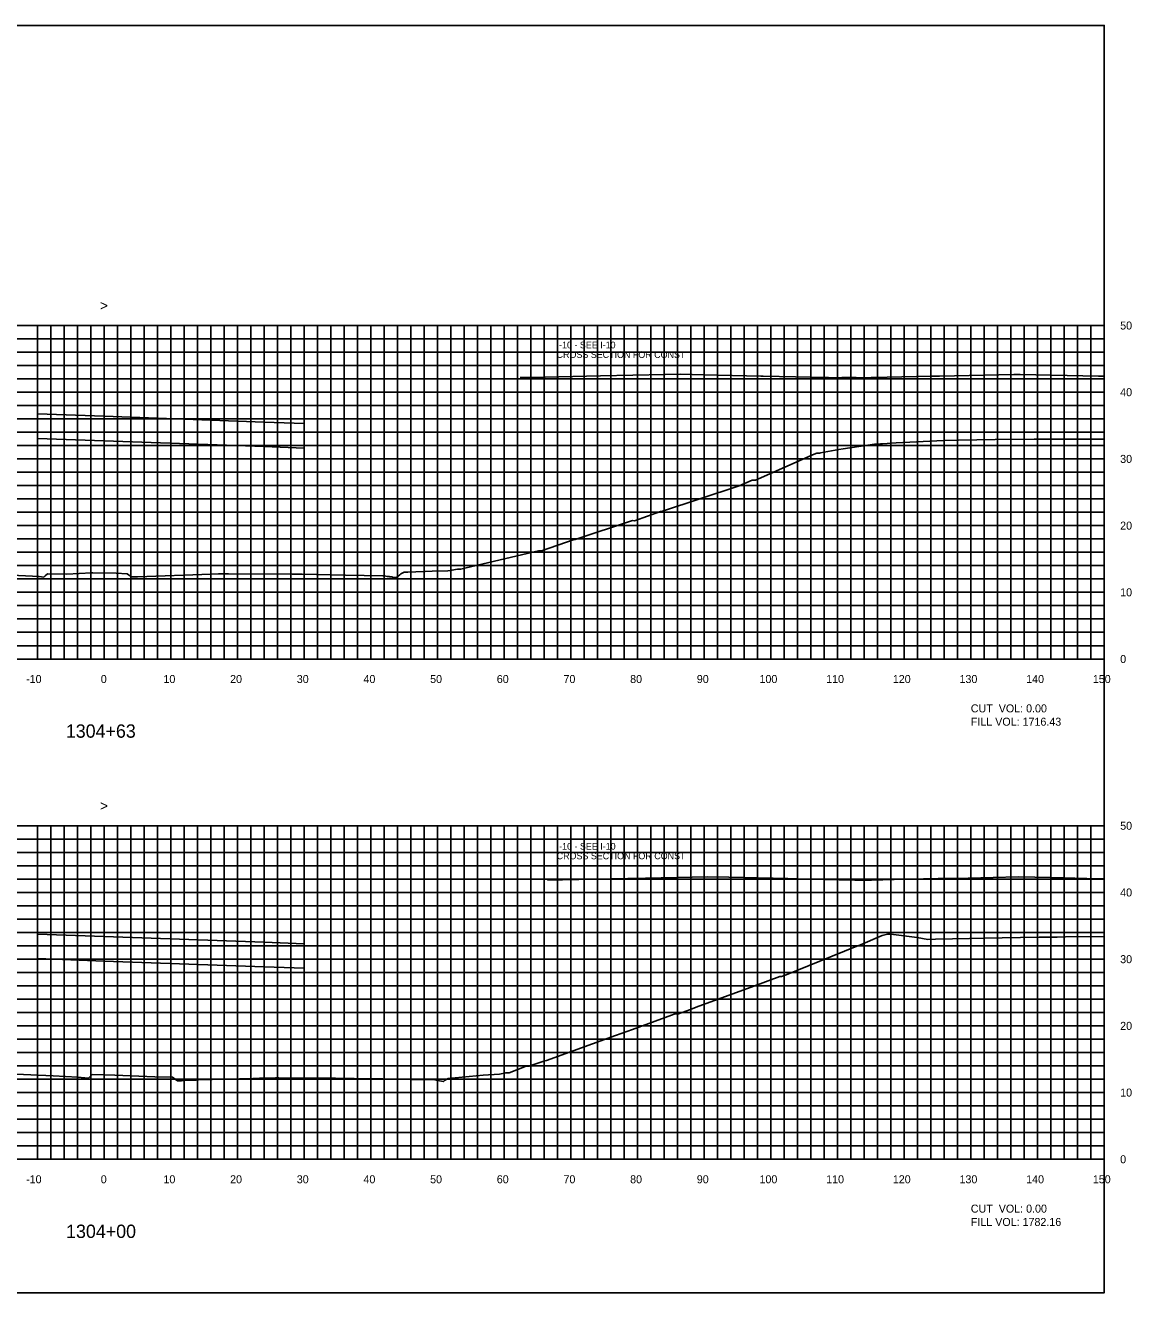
# Model space of a CAD drawing. Extents: x 1797714 to 1804825, y 249015 to 250269.
# Drawn here: x 1803639.2 to 1803805.1, y 250079.4 to 250269.4 of the extents above; entities that cross this region are included whole.
import ezdxf

# ---------------------------------------------------------------- set-up
doc = ezdxf.new("R2010")
doc.units = 0
for name, color, linetype in [('1', 7, 'Continuous'), ('10', 7, 'Continuous'), ('3', 7, 'Continuous'), ('31', 7, 'Continuous'), ('60', 7, 'Continuous'), ('ANNO-TXT', 7, 'Continuous'), ('BRG-DECK', 7, 'Continuous'), ('CL-CNST', 7, 'Continuous'), ('Level 62', 7, 'Continuous'), ('M-ROADS', 7, 'Continuous')]:
    doc.layers.add(name, color=color, linetype=linetype)

msp = doc.modelspace()

# ---------------------------------------------------------------- linework, layer by layer
msp.add_lwpolyline([(1803501, 250079.43), (1803801, 250079.43), (1803801, 250269.43), (1803501, 250269.43)], close=True)
at = {"layer": '60'}
for p, q in [((1803801, 250174.43), (1803801, 250224.43)), ((1803801.06, 250224.43), (1803801, 250224.43)), ((1803801.06, 250214.43), (1803801, 250214.43)), ((1803801.06, 250204.43), (1803801, 250204.43)), ((1803801.06, 250194.43), (1803801, 250194.43)), ((1803801.06, 250184.43), (1803801, 250184.43)), ((1803501, 250174.43), (1803801, 250174.43)), ((1803641, 250174.37), (1803641, 250174.43)), ((1803651, 250174.37), (1803651, 250174.43)), ((1803661, 250174.37), (1803661, 250174.43)), ((1803671, 250174.37), (1803671, 250174.43)), ((1803681, 250174.37), (1803681, 250174.43)), ((1803691, 250174.37), (1803691, 250174.43)), ((1803701, 250174.37), (1803701, 250174.43)), ((1803711, 250174.37), (1803711, 250174.43)), ((1803721, 250174.37), (1803721, 250174.43)), ((1803731, 250174.37), (1803731, 250174.43)), ((1803741, 250174.37), (1803741, 250174.43)), ((1803751, 250174.37), (1803751, 250174.43)), ((1803761, 250174.37), (1803761, 250174.43)), ((1803771, 250174.37), (1803771, 250174.43)), ((1803781, 250174.37), (1803781, 250174.43)), ((1803791, 250174.37), (1803791, 250174.43)), ((1803801, 250174.37), (1803801, 250174.43)), ((1803801.06, 250174.43), (1803801, 250174.43)), ((1803801, 250099.43), (1803801, 250149.43)), ((1803801.06, 250149.43), (1803801, 250149.43)), ((1803801.06, 250139.43), (1803801, 250139.43)), ((1803801.06, 250129.43), (1803801, 250129.43)), ((1803801.06, 250119.43), (1803801, 250119.43)), ((1803801.06, 250109.43), (1803801, 250109.43)), ((1803501, 250099.43), (1803801, 250099.43)), ((1803641, 250099.37), (1803641, 250099.43)), ((1803651, 250099.37), (1803651, 250099.43)), ((1803661, 250099.37), (1803661, 250099.43)), ((1803671, 250099.37), (1803671, 250099.43)), ((1803681, 250099.37), (1803681, 250099.43)), ((1803691, 250099.37), (1803691, 250099.43)), ((1803701, 250099.37), (1803701, 250099.43)), ((1803711, 250099.37), (1803711, 250099.43)), ((1803721, 250099.37), (1803721, 250099.43)), ((1803731, 250099.37), (1803731, 250099.43)), ((1803741, 250099.37), (1803741, 250099.43)), ((1803751, 250099.37), (1803751, 250099.43)), ((1803761, 250099.37), (1803761, 250099.43)), ((1803771, 250099.37), (1803771, 250099.43)), ((1803781, 250099.37), (1803781, 250099.43)), ((1803791, 250099.37), (1803791, 250099.43)), ((1803801, 250099.37), (1803801, 250099.43)), ((1803801.06, 250099.43), (1803801, 250099.43))]:
    msp.add_line(p, q, dxfattribs=at)
at = {"layer": 'BRG-DECK'}
for points in [[(1803681, 250206.06), (1803681, 250209.74), (1803675, 250209.95), (1803651, 250210.82), (1803641, 250211.18), (1803641, 250207.5), (1803651, 250207.14), (1803675, 250206.27)], [(1803681, 250128.07), (1803681, 250131.75), (1803675, 250131.97), (1803651, 250132.83), (1803641, 250133.19), (1803641, 250129.51), (1803651, 250129.15), (1803675, 250128.29)]]:
    msp.add_lwpolyline(points, close=True, dxfattribs=at)
at = {"layer": 'CL-CNST'}
for points in [[(1803713.39, 250216.62), (1803715.06, 250216.65), (1803725.43, 250216.88), (1803735.14, 250217.08), (1803737.47, 250217.13), (1803740.95, 250217.06), (1803749.51, 250216.86), (1803749.84, 250216.86), (1803759.55, 250216.64), (1803759.63, 250216.64), (1803760.8, 250216.61), (1803760.8, 250216.61), (1803760.89, 250216.61), (1803761.66, 250216.63), (1803762.67, 250216.65), (1803763.78, 250216.63), (1803765.01, 250216.61)], [(1803765.01, 250216.61), (1803766.06, 250216.63), (1803766.27, 250216.63), (1803775.05, 250216.82), (1803776.32, 250216.85), (1803787.46, 250217.09), (1803788.38, 250217.11), (1803800.14, 250216.84), (1803800.44, 250216.83), (1803801, 250216.82)], [(1803641, 250211.18), (1803651, 250210.82), (1803675, 250209.95), (1803681, 250209.74)], [(1803717.52, 250141.25), (1803719.73, 250141.3), (1803729.53, 250141.51), (1803732.21, 250141.57), (1803741.55, 250141.77), (1803744.7, 250141.7), (1803753.57, 250141.5), (1803756.56, 250141.44), (1803763.58, 250141.28), (1803763.98, 250141.27), (1803764.83, 250141.25), (1803764.83, 250141.25), (1803764.83, 250141.25), (1803765.24, 250141.26), (1803766.08, 250141.28), (1803769.48, 250141.35), (1803776.1, 250141.5), (1803780.6, 250141.59), (1803788.11, 250141.76), (1803793.08, 250141.65), (1803800.13, 250141.49), (1803801, 250141.47)], [(1803641, 250133.19), (1803651, 250132.83), (1803675, 250131.97), (1803681, 250131.75)]]:
    msp.add_lwpolyline(points, dxfattribs=at)
at = {"layer": 'Level 62'}
for p, q in [((1803501, 250224.43), (1803801, 250224.43)), ((1803641, 250174.43), (1803641, 250224.43)), ((1803643, 250174.43), (1803643, 250224.43)), ((1803645, 250174.43), (1803645, 250224.43)), ((1803647, 250174.43), (1803647, 250224.43)), ((1803649, 250174.43), (1803649, 250224.43)), ((1803651, 250174.43), (1803651, 250224.43)), ((1803653, 250174.43), (1803653, 250224.43)), ((1803655, 250174.43), (1803655, 250224.43)), ((1803657, 250174.43), (1803657, 250224.43)), ((1803659, 250174.43), (1803659, 250224.43)), ((1803661, 250174.43), (1803661, 250224.43)), ((1803663, 250174.43), (1803663, 250224.43)), ((1803665, 250174.43), (1803665, 250224.43)), ((1803667, 250174.43), (1803667, 250224.43)), ((1803669, 250174.43), (1803669, 250224.43)), ((1803671, 250174.43), (1803671, 250224.43)), ((1803673, 250174.43), (1803673, 250224.43)), ((1803675, 250174.43), (1803675, 250224.43)), ((1803677, 250174.43), (1803677, 250224.43)), ((1803679, 250174.43), (1803679, 250224.43)), ((1803681, 250174.43), (1803681, 250224.43)), ((1803683, 250174.43), (1803683, 250224.43)), ((1803685, 250174.43), (1803685, 250224.43)), ((1803687, 250174.43), (1803687, 250224.43)), ((1803689, 250174.43), (1803689, 250224.43)), ((1803691, 250174.43), (1803691, 250224.43)), ((1803693, 250174.43), (1803693, 250224.43)), ((1803695, 250174.43), (1803695, 250224.43)), ((1803697, 250174.43), (1803697, 250224.43)), ((1803699, 250174.43), (1803699, 250224.43)), ((1803701, 250174.43), (1803701, 250224.43)), ((1803703, 250174.43), (1803703, 250224.43)), ((1803705, 250174.43), (1803705, 250224.43)), ((1803707, 250174.43), (1803707, 250224.43)), ((1803709, 250174.43), (1803709, 250224.43)), ((1803711, 250174.43), (1803711, 250224.43)), ((1803713, 250174.43), (1803713, 250224.43)), ((1803715, 250174.43), (1803715, 250224.43)), ((1803717, 250174.43), (1803717, 250224.43)), ((1803719, 250174.43), (1803719, 250224.43)), ((1803721, 250174.43), (1803721, 250224.43)), ((1803723, 250174.43), (1803723, 250224.43)), ((1803725, 250174.43), (1803725, 250224.43)), ((1803727, 250174.43), (1803727, 250224.43)), ((1803729, 250174.43), (1803729, 250224.43)), ((1803731, 250174.43), (1803731, 250224.43)), ((1803733, 250174.43), (1803733, 250224.43)), ((1803735, 250174.43), (1803735, 250224.43)), ((1803737, 250174.43), (1803737, 250224.43)), ((1803739, 250174.43), (1803739, 250224.43)), ((1803741, 250174.43), (1803741, 250224.43)), ((1803743, 250174.43), (1803743, 250224.43)), ((1803745, 250174.43), (1803745, 250224.43)), ((1803747, 250174.43), (1803747, 250224.43)), ((1803749, 250174.43), (1803749, 250224.43)), ((1803751, 250174.43), (1803751, 250224.43)), ((1803753, 250174.43), (1803753, 250224.43)), ((1803755, 250174.43), (1803755, 250224.43)), ((1803757, 250174.43), (1803757, 250224.43)), ((1803759, 250174.43), (1803759, 250224.43)), ((1803761, 250174.43), (1803761, 250224.43)), ((1803763, 250174.43), (1803763, 250224.43)), ((1803765, 250174.43), (1803765, 250224.43)), ((1803767, 250174.43), (1803767, 250224.43)), ((1803769, 250174.43), (1803769, 250224.43)), ((1803771, 250174.43), (1803771, 250224.43)), ((1803773, 250174.43), (1803773, 250224.43)), ((1803775, 250174.43), (1803775, 250224.43)), ((1803777, 250174.43), (1803777, 250224.43)), ((1803779, 250174.43), (1803779, 250224.43)), ((1803781, 250174.43), (1803781, 250224.43)), ((1803783, 250174.43), (1803783, 250224.43)), ((1803785, 250174.43), (1803785, 250224.43)), ((1803787, 250174.43), (1803787, 250224.43)), ((1803789, 250174.43), (1803789, 250224.43)), ((1803791, 250174.43), (1803791, 250224.43)), ((1803793, 250174.43), (1803793, 250224.43)), ((1803795, 250174.43), (1803795, 250224.43)), ((1803797, 250174.43), (1803797, 250224.43)), ((1803799, 250174.43), (1803799, 250224.43)), ((1803801, 250174.43), (1803801, 250224.43)), ((1803501, 250222.43), (1803801, 250222.43)), ((1803501, 250220.43), (1803801, 250220.43)), ((1803501, 250218.43), (1803801, 250218.43)), ((1803501, 250216.43), (1803801, 250216.43)), ((1803501, 250214.43), (1803801, 250214.43)), ((1803501, 250212.43), (1803801, 250212.43)), ((1803501, 250210.43), (1803801, 250210.43)), ((1803501, 250208.43), (1803801, 250208.43)), ((1803501, 250206.43), (1803801, 250206.43)), ((1803501, 250204.43), (1803801, 250204.43)), ((1803501, 250202.43), (1803801, 250202.43)), ((1803501, 250200.43), (1803801, 250200.43)), ((1803501, 250198.43), (1803801, 250198.43)), ((1803501, 250196.43), (1803801, 250196.43)), ((1803501, 250194.43), (1803801, 250194.43)), ((1803501, 250192.43), (1803801, 250192.43)), ((1803501, 250190.43), (1803801, 250190.43)), ((1803501, 250188.43), (1803801, 250188.43)), ((1803501, 250186.43), (1803801, 250186.43)), ((1803501, 250184.43), (1803801, 250184.43)), ((1803501, 250182.43), (1803801, 250182.43)), ((1803501, 250180.43), (1803801, 250180.43)), ((1803501, 250178.43), (1803801, 250178.43)), ((1803501, 250176.43), (1803801, 250176.43)), ((1803501, 250174.43), (1803801, 250174.43)), ((1803501, 250149.43), (1803801, 250149.43)), ((1803641, 250099.43), (1803641, 250149.43)), ((1803643, 250099.43), (1803643, 250149.43)), ((1803645, 250099.43), (1803645, 250149.43)), ((1803647, 250099.43), (1803647, 250149.43)), ((1803649, 250099.43), (1803649, 250149.43)), ((1803651, 250099.43), (1803651, 250149.43)), ((1803653, 250099.43), (1803653, 250149.43)), ((1803655, 250099.43), (1803655, 250149.43)), ((1803657, 250099.43), (1803657, 250149.43)), ((1803659, 250099.43), (1803659, 250149.43)), ((1803661, 250099.43), (1803661, 250149.43)), ((1803663, 250099.43), (1803663, 250149.43)), ((1803665, 250099.43), (1803665, 250149.43)), ((1803667, 250099.43), (1803667, 250149.43)), ((1803669, 250099.43), (1803669, 250149.43)), ((1803671, 250099.43), (1803671, 250149.43)), ((1803673, 250099.43), (1803673, 250149.43)), ((1803675, 250099.43), (1803675, 250149.43)), ((1803677, 250099.43), (1803677, 250149.43)), ((1803679, 250099.43), (1803679, 250149.43)), ((1803681, 250099.43), (1803681, 250149.43)), ((1803683, 250099.43), (1803683, 250149.43)), ((1803685, 250099.43), (1803685, 250149.43)), ((1803687, 250099.43), (1803687, 250149.43)), ((1803689, 250099.43), (1803689, 250149.43)), ((1803691, 250099.43), (1803691, 250149.43)), ((1803693, 250099.43), (1803693, 250149.43)), ((1803695, 250099.43), (1803695, 250149.43)), ((1803697, 250099.43), (1803697, 250149.43)), ((1803699, 250099.43), (1803699, 250149.43)), ((1803701, 250099.43), (1803701, 250149.43)), ((1803703, 250099.43), (1803703, 250149.43)), ((1803705, 250099.43), (1803705, 250149.43)), ((1803707, 250099.43), (1803707, 250149.43)), ((1803709, 250099.43), (1803709, 250149.43)), ((1803711, 250099.43), (1803711, 250149.43)), ((1803713, 250099.43), (1803713, 250149.43)), ((1803715, 250099.43), (1803715, 250149.43)), ((1803717, 250099.43), (1803717, 250149.43)), ((1803719, 250099.43), (1803719, 250149.43)), ((1803721, 250099.43), (1803721, 250149.43)), ((1803723, 250099.43), (1803723, 250149.43)), ((1803725, 250099.43), (1803725, 250149.43)), ((1803727, 250099.43), (1803727, 250149.43)), ((1803729, 250099.43), (1803729, 250149.43)), ((1803731, 250099.43), (1803731, 250149.43)), ((1803733, 250099.43), (1803733, 250149.43)), ((1803735, 250099.43), (1803735, 250149.43)), ((1803737, 250099.43), (1803737, 250149.43)), ((1803739, 250099.43), (1803739, 250149.43)), ((1803741, 250099.43), (1803741, 250149.43)), ((1803743, 250099.43), (1803743, 250149.43)), ((1803745, 250099.43), (1803745, 250149.43)), ((1803747, 250099.43), (1803747, 250149.43)), ((1803749, 250099.43), (1803749, 250149.43)), ((1803751, 250099.43), (1803751, 250149.43)), ((1803753, 250099.43), (1803753, 250149.43)), ((1803755, 250099.43), (1803755, 250149.43)), ((1803757, 250099.43), (1803757, 250149.43)), ((1803759, 250099.43), (1803759, 250149.43)), ((1803761, 250099.43), (1803761, 250149.43)), ((1803763, 250099.43), (1803763, 250149.43)), ((1803765, 250099.43), (1803765, 250149.43)), ((1803767, 250099.43), (1803767, 250149.43)), ((1803769, 250099.43), (1803769, 250149.43)), ((1803771, 250099.43), (1803771, 250149.43)), ((1803773, 250099.43), (1803773, 250149.43)), ((1803775, 250099.43), (1803775, 250149.43)), ((1803777, 250099.43), (1803777, 250149.43)), ((1803779, 250099.43), (1803779, 250149.43)), ((1803781, 250099.43), (1803781, 250149.43)), ((1803783, 250099.43), (1803783, 250149.43)), ((1803785, 250099.43), (1803785, 250149.43)), ((1803787, 250099.43), (1803787, 250149.43)), ((1803789, 250099.43), (1803789, 250149.43)), ((1803791, 250099.43), (1803791, 250149.43)), ((1803793, 250099.43), (1803793, 250149.43)), ((1803795, 250099.43), (1803795, 250149.43)), ((1803797, 250099.43), (1803797, 250149.43)), ((1803799, 250099.43), (1803799, 250149.43)), ((1803801, 250099.43), (1803801, 250149.43)), ((1803501, 250147.43), (1803801, 250147.43)), ((1803501, 250145.43), (1803801, 250145.43)), ((1803501, 250143.43), (1803801, 250143.43)), ((1803501, 250141.43), (1803801, 250141.43)), ((1803501, 250139.43), (1803801, 250139.43)), ((1803501, 250137.43), (1803801, 250137.43)), ((1803501, 250135.43), (1803801, 250135.43)), ((1803501, 250133.43), (1803801, 250133.43)), ((1803501, 250131.43), (1803801, 250131.43)), ((1803501, 250129.43), (1803801, 250129.43)), ((1803501, 250127.43), (1803801, 250127.43)), ((1803501, 250125.43), (1803801, 250125.43)), ((1803501, 250123.43), (1803801, 250123.43)), ((1803501, 250121.43), (1803801, 250121.43)), ((1803501, 250119.43), (1803801, 250119.43)), ((1803501, 250117.43), (1803801, 250117.43)), ((1803501, 250115.43), (1803801, 250115.43)), ((1803501, 250113.43), (1803801, 250113.43)), ((1803501, 250111.43), (1803801, 250111.43)), ((1803501, 250109.43), (1803801, 250109.43)), ((1803501, 250107.43), (1803801, 250107.43)), ((1803501, 250105.43), (1803801, 250105.43)), ((1803501, 250103.43), (1803801, 250103.43)), ((1803501, 250101.43), (1803801, 250101.43)), ((1803501, 250099.43), (1803801, 250099.43))]:
    msp.add_line(p, q, dxfattribs=at)
at = {"layer": 'M-ROADS'}
for points in [[(1803630.81, 250187.31), (1803640.28, 250186.86), (1803640.9, 250186.8), (1803641.24, 250186.78), (1803641.95, 250186.71), (1803642.14, 250186.88), (1803642.49, 250187.2), (1803645.43, 250187.14), (1803649.11, 250187.33), (1803649.31, 250187.33), (1803652.82, 250187.28), (1803654.44, 250187.22), (1803654.67, 250187.06), (1803655.1, 250186.74), (1803655.9, 250186.75), (1803655.94, 250186.75), (1803655.98, 250186.75), (1803656.01, 250186.75), (1803667.08, 250187.15), (1803668.16, 250187.19), (1803668.63, 250187.18), (1803669.55, 250187.19), (1803669.67, 250187.19), (1803679.21, 250187.15), (1803680.7, 250187.15), (1803687.21, 250187.02), (1803692.79, 250186.92), (1803692.97, 250186.89), (1803693.08, 250186.88), (1803693.26, 250186.85), (1803693.47, 250186.82), (1803693.63, 250186.8), (1803693.76, 250186.78), (1803693.87, 250186.77), (1803693.96, 250186.76), (1803694.03, 250186.75), (1803694.09, 250186.74), (1803694.14, 250186.74), (1803694.19, 250186.73), (1803694.23, 250186.72), (1803694.27, 250186.72), (1803694.3, 250186.71), (1803694.86, 250186.66), (1803695.35, 250187.06), (1803695.44, 250187.13), (1803695.51, 250187.21), (1803696.02, 250187.43), (1803696.04, 250187.43), (1803696.04, 250187.43), (1803696.52, 250187.43), (1803696.54, 250187.43), (1803697.74, 250187.48), (1803699.18, 250187.54), (1803700.2, 250187.58), (1803702.55, 250187.66), (1803703.06, 250187.72), (1803703.16, 250187.73), (1803704.01, 250187.91), (1803704.5, 250187.92), (1803705.29, 250188.08), (1803716.18, 250190.67), (1803716.39, 250190.66), (1803716.61, 250190.64), (1803721.49, 250192.33), (1803721.67, 250192.34), (1803730.24, 250195.18), (1803730.54, 250195.17), (1803734.46, 250196.55), (1803734.62, 250196.56), (1803746.24, 250200.38), (1803748.19, 250201.23), (1803748.49, 250201.25), (1803748.72, 250201.26), (1803757.49, 250205.15), (1803757.89, 250205.31), (1803758.06, 250205.31), (1803758.19, 250205.31), (1803758.4, 250205.31), (1803758.44, 250205.33), (1803761.21, 250205.84), (1803761.86, 250205.95), (1803766.57, 250206.62), (1803767.45, 250206.68), (1803767.77, 250206.69), (1803769.81, 250206.84), (1803776.92, 250207.17), (1803779.16, 250207.26), (1803784.64, 250207.33), (1803790.51, 250207.38), (1803797.11, 250207.38), (1803801, 250207.37)], [(1803634.43, 250112.34), (1803643.37, 250111.95), (1803647.05, 250111.73), (1803647.57, 250111.68), (1803648.67, 250111.61), (1803648.82, 250111.75), (1803649.22, 250112.12), (1803652.59, 250112.02), (1803658.63, 250111.8), (1803661.28, 250111.72), (1803661.85, 250111.28), (1803662.02, 250111.17), (1803662.19, 250111.18), (1803662.33, 250111.18), (1803662.6, 250111.2), (1803663.62, 250111.27), (1803664.83, 250111.31), (1803665.15, 250111.32), (1803671.31, 250111.49), (1803673.32, 250111.54), (1803674.31, 250111.57), (1803674.46, 250111.58), (1803674.9, 250111.58), (1803676.73, 250111.62), (1803676.78, 250111.62), (1803677.21, 250111.62), (1803680.35, 250111.61), (1803680.59, 250111.61), (1803681.89, 250111.6), (1803685.24, 250111.57), (1803685.73, 250111.57), (1803688.5, 250111.56), (1803692.81, 250111.47), (1803693.45, 250111.46), (1803700.59, 250111.32), (1803701, 250111.24), (1803701.93, 250111.08), (1803702.08, 250111.23), (1803702.59, 250111.54), (1803707.84, 250112.05), (1803710.3, 250112.19), (1803711.25, 250112.41), (1803711.49, 250112.41), (1803711.75, 250112.41), (1803714.32, 250113.37), (1803714.75, 250113.39), (1803714.87, 250113.44), (1803716.95, 250114.12), (1803717.38, 250114.26), (1803727.72, 250118.01), (1803730.25, 250118.91), (1803736.09, 250121.02), (1803736.64, 250121.23), (1803736.66, 250121.23), (1803737.15, 250121.23), (1803738.8, 250121.83), (1803738.97, 250121.89), (1803739.8, 250122.22), (1803748.46, 250125.37), (1803752.33, 250126.84), (1803752.59, 250126.82), (1803752.77, 250126.88), (1803753.05, 250126.98), (1803763.88, 250131.4), (1803764.12, 250131.41), (1803767.68, 250132.99), (1803768.49, 250133.16), (1803768.75, 250133.17), (1803769.01, 250133.17), (1803772.97, 250132.69), (1803774.55, 250132.38), (1803775.68, 250132.41), (1803780.82, 250132.54), (1803782.91, 250132.6), (1803791.26, 250132.71), (1803793.97, 250132.75), (1803795.18, 250132.76), (1803801, 250132.83)]]:
    msp.add_lwpolyline(points, dxfattribs=at)

# ---------------------------------------------------------------- texts
at = {"layer": '1'}
for s, p in [('1304+63', (1803645.26, 250162.63)), ('1304+00', (1803645.3, 250087.63))]:
    msp.add_text(s, height=2, dxfattribs=at).set_placement(p)
at = {"layer": '10'}
for s, p in [('-10', (1803639.3, 250170.83)), ('0', (1803650.5, 250170.83)), ('10', (1803659.9, 250170.83)), ('20', (1803669.9, 250170.83)), ('30', (1803679.9, 250170.83)), ('40', (1803689.9, 250170.83)), ('50', (1803699.9, 250170.83)), ('60', (1803709.9, 250170.83)), ('70', (1803719.9, 250170.83)), ('80', (1803729.9, 250170.83)), ('90', (1803739.9, 250170.83)), ('100', (1803749.3, 250170.83)), ('110', (1803759.3, 250170.83)), ('120', (1803769.3, 250170.83)), ('130', (1803779.3, 250170.83)), ('140', (1803789.3, 250170.83)), ('150', (1803799.3, 250170.83)), ('-10', (1803639.3, 250095.83)), ('0', (1803650.5, 250095.83)), ('10', (1803659.9, 250095.83)), ('20', (1803669.9, 250095.83)), ('30', (1803679.9, 250095.83)), ('40', (1803689.9, 250095.83)), ('50', (1803699.9, 250095.83)), ('60', (1803709.9, 250095.83)), ('70', (1803719.9, 250095.83)), ('80', (1803729.9, 250095.83)), ('90', (1803739.9, 250095.83)), ('100', (1803749.3, 250095.83)), ('110', (1803759.3, 250095.83)), ('120', (1803769.3, 250095.83)), ('130', (1803779.3, 250095.83)), ('140', (1803789.3, 250095.83)), ('150', (1803799.3, 250095.83))]:
    msp.add_text(s, height=1.2, dxfattribs=at).set_placement(p)
at = {"layer": '3'}
for s, p in [('CROSS SECTION FOR CONST ', (1803718.87, 250219.57)), ('I-10 - SEE I-10 ', (1803718.87, 250221.01)), ('I-10 - SEE I-10 ', (1803718.88, 250145.85)), ('CROSS SECTION FOR CONST ', (1803718.88, 250144.41))]:
    msp.add_text(s, height=1, dxfattribs=at).set_placement(p)
at = {"layer": '31'}
for s, p in [('50', (1803803.4, 250223.83)), ('40', (1803803.4, 250213.83)), ('30', (1803803.4, 250203.83)), ('20', (1803803.4, 250193.83)), ('10', (1803803.4, 250183.83)), ('0', (1803803.4, 250173.83)), ('50', (1803803.4, 250148.83)), ('40', (1803803.4, 250138.83)), ('30', (1803803.4, 250128.83)), ('20', (1803803.4, 250118.83)), ('10', (1803803.4, 250108.83)), ('0', (1803803.4, 250098.83))]:
    msp.add_text(s, height=1.2, dxfattribs=at).set_placement(p)
at = {"layer": '60'}
for p in [(1803650.39, 250226.68), (1803650.39, 250151.68)]:
    msp.add_text('>', height=1.5, dxfattribs=at).set_placement(p)
at = {"layer": 'ANNO-TXT'}
for s, p in [('CUT  VOL: 0.00', (1803781, 250166.43)), ('FILL VOL: 1716.43', (1803781, 250164.43)), ('CUT  VOL: 0.00', (1803781, 250091.43)), ('FILL VOL: 1782.16', (1803781, 250089.43))]:
    msp.add_text(s, height=1.2, dxfattribs=at).set_placement(p)

doc.saveas('drawing.dxf')
